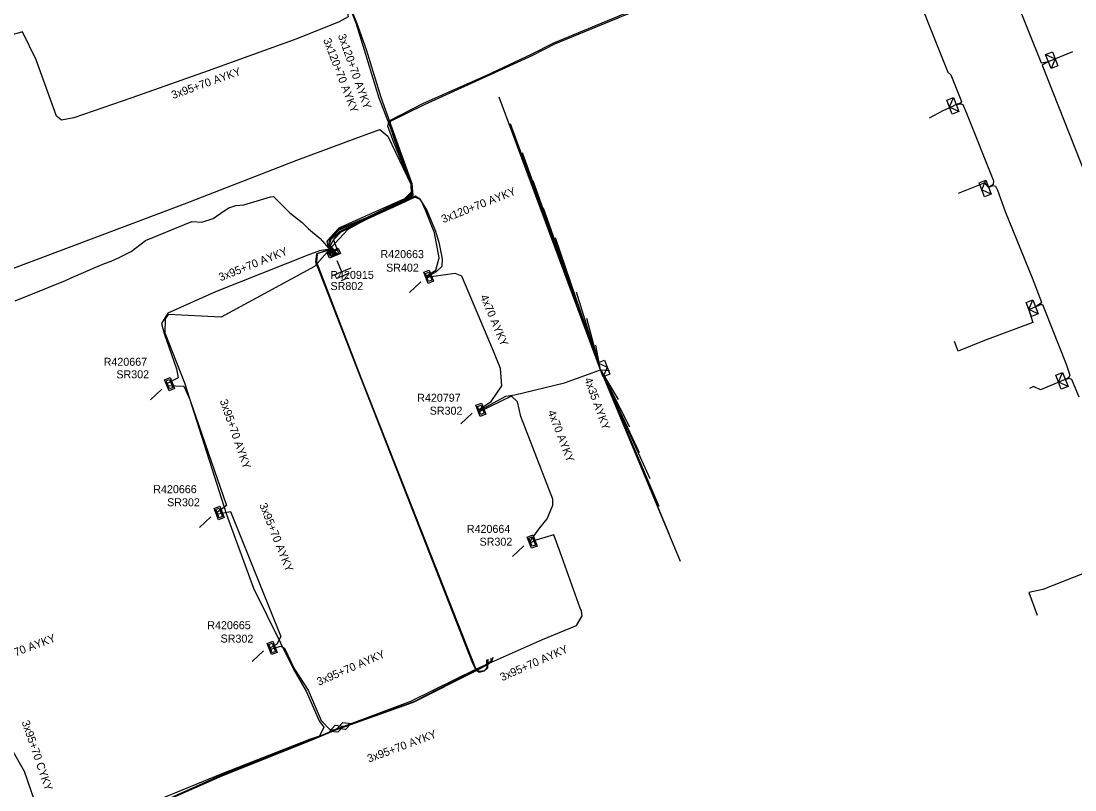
# Model space of a CAD drawing. Extents: x -540028 to -538776, y -1157064 to -1155670.
# Drawn here: x -539818.5 to -539686.8, y -1156414.7 to -1156318.7 of the extents above; entities that cross this region are included whole.
import ezdxf

# ---------------------------------------------------------------- set-up
doc = ezdxf.new("R2010")
doc.units = 0
for name, color, linetype in [('Vrstva 15', 7, 'Continuous'), ('Vrstva 19', 7, 'Continuous'), ('Vrstva 2', 7, 'Continuous'), ('Vrstva 28', 7, 'Continuous'), ('Vrstva 29', 7, 'Continuous'), ('Vrstva 30', 7, 'Continuous'), ('Vrstva 31', 7, 'Continuous'), ('Vrstva 5', 7, 'Continuous'), ('Vrstva 52', 7, 'Continuous'), ('Vrstva 59', 7, 'Continuous'), ('Vrstva 6', 7, 'Continuous'), ('Vrstva 9', 7, 'Continuous')]:
    doc.layers.add(name, color=color, linetype=linetype)

# ---------------------------------------------------------------- blocks, each defined once
blk = doc.blocks.new('17')
at = {"layer": 'Vrstva 2'}
blk.add_lwpolyline([(-1.875, 0), (0, 0.9375), (1.875, 0), (0, -0.9375)], close=True, dxfattribs=at)
blk = doc.blocks.new('132')
at = {"layer": 'Vrstva 2'}
for points in [[(-1.5, 1.5), (1.5, 1.5), (1.5, 0), (-1.5, 0)], [(-1.1, 1.2), (1.1, 1.2), (1.1, 0.3), (-1.1, 0.3)]]:
    blk.add_lwpolyline(points, close=True, dxfattribs=at)
blk = doc.blocks.new('23')
at = {"layer": 'Vrstva 2'}
blk.add_lwpolyline([(1.875, -1.8), (-1.875, -1.8), (-1.875, 0), (1.875, 0)], close=True, dxfattribs=at)
blk.add_lwpolyline([(1.875, 0), (0, -1.8), (-1.875, 0)], dxfattribs=at)
blk = doc.blocks.new('11')
at = {"layer": 'Vrstva 2'}
for p, q in [((0, -4.3), (0, -1.3)), ((-2.5, -4.3), (2.5, -4.3)), ((-1.7, -5.3), (1.7, -5.3)), ((-0.9, -6.3), (0.9, -6.3))]:
    blk.add_line(p, q, dxfattribs=at)

msp = doc.modelspace()

# ---------------------------------------------------------------- linework, layer by layer
at = {"layer": 'Vrstva 5'}
for points in [[(-539779, -1156347.91), (-539779.95, -1156346.73), (-539779.73, -1156345.88), (-539778.61, -1156344.9), (-539775.24, -1156343.33), (-539770.56, -1156341.04), (-539769.48, -1156340.33), (-539769.63, -1156339.03), (-539771.64, -1156333.68), (-539773.7, -1156328.29), (-539775.54, -1156322.32), (-539776.58, -1156318.93), (-539779.82, -1156310.93), (-539785.14, -1156296.81), (-539791.02, -1156282.92), (-539792.28, -1156279.49), (-539793.49, -1156277.84), (-539795.98, -1156277.37), (-539798.25, -1156277.83), (-539804.23, -1156280.56), (-539807.94, -1156282.09), (-539808.56, -1156282.83), (-539808.18, -1156284.31), (-539807.82, -1156285.1)], [(-539779.43, -1156348.07), (-539780.03, -1156346.76), (-539779.79, -1156345.7), (-539778.81, -1156344.68), (-539775.19, -1156343.16), (-539770.61, -1156340.97), (-539769.67, -1156340.19), (-539769.72, -1156339.08), (-539771.9, -1156333.83), (-539772.63, -1156331.81), (-539772.46, -1156331.12), (-539768.16, -1156328.91), (-539760.28, -1156325.42), (-539754.68, -1156322.8), (-539751.87, -1156321.38), (-539734.78, -1156314.29), (-539723.45, -1156309.64), (-539721.79, -1156309.32), (-539716.19, -1156306.53), (-539715.16, -1156306), (-539714.89, -1156306.22)], [(-539779.1, -1156347.94), (-539779.99, -1156346.75), (-539779.78, -1156345.83), (-539778.71, -1156344.76), (-539775.28, -1156343.26), (-539770.58, -1156340.98), (-539769.62, -1156340.26), (-539769.67, -1156339.06), (-539771.71, -1156333.71), (-539772.29, -1156331.91), (-539772.31, -1156331.17), (-539768.05, -1156329.1), (-539760.25, -1156325.54), (-539754.53, -1156322.92), (-539751.76, -1156321.51), (-539734.73, -1156314.46), (-539723.4, -1156309.72), (-539721.66, -1156309.44), (-539716.13, -1156306.73), (-539715.24, -1156306.18), (-539715.07, -1156306.3)], [(-539786.69, -1156308.23), (-539786.54, -1156308.51), (-539785.86, -1156308.98), (-539783.04, -1156307.79), (-539782.4, -1156307.75), (-539781.84, -1156308.29), (-539779.58, -1156313.15), (-539777.72, -1156317.26), (-539777.6, -1156318.14), (-539778.7, -1156318.77), (-539784.02, -1156320.88), (-539795.1, -1156324.88), (-539804.64, -1156328.28), (-539811.88, -1156330.75), (-539813.44, -1156331.06), (-539814.03, -1156330.55), (-539816.6, -1156323.5), (-539818.29, -1156320), (-539820, -1156320.5)], [(-539778.89, -1156347.86), (-539779.8, -1156346.69), (-539779.52, -1156346.16), (-539779.42, -1156345.98), (-539778.58, -1156344.99), (-539775.24, -1156343.39), (-539770.51, -1156341.13), (-539769.45, -1156340.41), (-539769.59, -1156339.02), (-539771.53, -1156333.66), (-539773.45, -1156328.23), (-539775.31, -1156322.26), (-539776.5, -1156318.89), (-539779.74, -1156310.88)], [(-539707.85, -1156311.96), (-539702.63, -1156325.04), (-539702.28, -1156325.38), (-539700.92, -1156328.7), (-539701.06, -1156328.91), (-539701.6, -1156329.1), (-539701.03, -1156329.01), (-539700.77, -1156329.1), (-539700.31, -1156330.16), (-539696.92, -1156338.64), (-539696.97, -1156339.09), (-539697.56, -1156339.42), (-539696.96, -1156339.22), (-539696.68, -1156339.3), (-539696.43, -1156339.79), (-539695.46, -1156342.46), (-539692.12, -1156350.73), (-539690.95, -1156353.8), (-539691.1, -1156353.97), (-539691.68, -1156354.36), (-539691.07, -1156354.07), (-539690.83, -1156354.08), (-539690.47, -1156354.9), (-539687.84, -1156361.53), (-539687.38, -1156362.88), (-539687.5, -1156363.17), (-539687.96, -1156363.44), (-539687.47, -1156363.29), (-539687.19, -1156363.4), (-539686.27, -1156365.6)], [(-539695.93, -1156311.52), (-539690.98, -1156323.89), (-539690.08, -1156323.73), (-539690.86, -1156324.16), (-539685.43, -1156337.88)], [(-539819.22, -1156353.62), (-539812.92, -1156351.09), (-539812.21, -1156350.76), (-539808.82, -1156349.28), (-539808.03, -1156348.96), (-539807.23, -1156348.67), (-539806.14, -1156348.15), (-539804.73, -1156347.47), (-539802.91, -1156346.09), (-539797.15, -1156343.72), (-539795.87, -1156343.77), (-539794.45, -1156343.33), (-539793.09, -1156342.39), (-539792.51, -1156341.98), (-539791.62, -1156341.72), (-539790.62, -1156341.61), (-539787.28, -1156340.64), (-539786.93, -1156340.59), (-539784.89, -1156342.64), (-539783.35, -1156343.85), (-539782.55, -1156344.61), (-539781.09, -1156345.84), (-539779.23, -1156348)], [(-539767.92, -1156350.59), (-539766.65, -1156349.77), (-539766.2, -1156348.24), (-539766.79, -1156345.12), (-539767.91, -1156342.28), (-539768.53, -1156341), (-539769.25, -1156340.66), (-539770.46, -1156341.24), (-539775.2, -1156343.43), (-539778.52, -1156345.05), (-539779.41, -1156345.99), (-539778.74, -1156347.78)], [(-539779.59, -1156348.17), (-539780.03, -1156347.26), (-539780.16, -1156347.21), (-539781.19, -1156347.37), (-539782.63, -1156347.89), (-539794.17, -1156352.5), (-539800.14, -1156355.15), (-539800.91, -1156356.43), (-539800.59, -1156357.7), (-539799.03, -1156362.12), (-539798.85, -1156363.23), (-539800.3, -1156363.99)], [(-539761.39, -1156367.25), (-539759.73, -1156366.2), (-539758.39, -1156364.23), (-539758.54, -1156362.08), (-539759.41, -1156359.9), (-539763.38, -1156350.53), (-539764.2, -1156350.21), (-539767.49, -1156350.64), (-539767.82, -1156350.82)], [(-539761.34, -1156367.38), (-539757.9, -1156365.53), (-539756.77, -1156365.34), (-539750.57, -1156363.87), (-539746.05, -1156362.22)], [(-539800.22, -1156364.21), (-539798.14, -1156364.29), (-539797.39, -1156365.94), (-539792.78, -1156379.17), (-539794.09, -1156380.14)], [(-539754.94, -1156383.75), (-539753.64, -1156381.97), (-539752.7, -1156380.86), (-539752, -1156379.14), (-539752.02, -1156378.4), (-539756.03, -1156368.06), (-539756.43, -1156366.25), (-539757.18, -1156365.52), (-539761.29, -1156367.5)], [(-539794.04, -1156380.28), (-539792.29, -1156379.93), (-539786.01, -1156395.54), (-539786.49, -1156396.48), (-539787.46, -1156397.02)], [(-539778.09, -1156406.72), (-539769.74, -1156403.61), (-539761.56, -1156399.57), (-539753.31, -1156395.93), (-539749.05, -1156394.18), (-539748.36, -1156392.96), (-539748.45, -1156392.39), (-539748.61, -1156392), (-539750.88, -1156385.59), (-539751.9, -1156382.83), (-539754.13, -1156383.51), (-539754.89, -1156383.88)], [(-539787.4, -1156397.16), (-539786.05, -1156396.76), (-539785.55, -1156396.99), (-539784.28, -1156399.63), (-539782.6, -1156402.23), (-539780.95, -1156406.05), (-539779.83, -1156407.2), (-539779.26, -1156407.15), (-539779.04, -1156407.07)], [(-539779.04, -1156407.07), (-539778.09, -1156406.72)], [(-539853.12, -1156422.78), (-539851.98, -1156422.96), (-539849.68, -1156426.99), (-539846.07, -1156436.04), (-539845, -1156436.69), (-539844.1, -1156436.81), (-539843.07, -1156436.4), (-539825.27, -1156428.44), (-539815.27, -1156424.04), (-539814.92, -1156422.74), (-539815.01, -1156421.21), (-539815.55, -1156419.63), (-539818.05, -1156412.39), (-539819.4, -1156409.99), (-539820.22, -1156409.98)]]:
    msp.add_lwpolyline(points, dxfattribs=at)
at = {"layer": 'Vrstva 52'}
for points in [[(-539690.08, -1156323.73), (-539687, -1156322.49)], [(-539701.6, -1156329.1), (-539702.04, -1156329.34), (-539703.28, -1156329.88), (-539704.99, -1156330.81)], [(-539697.56, -1156339.42), (-539698.02, -1156338.86), (-539701.34, -1156340.22)], [(-539691.68, -1156354.36), (-539692.54, -1156354.75), (-539692.04, -1156356.33), (-539698.04, -1156358.58), (-539701.35, -1156359.89), (-539701.82, -1156358.69)], [(-539687.96, -1156363.44), (-539691.07, -1156364.75), (-539691.95, -1156364.31), (-539692.42, -1156364.57)], [(-539679.72, -1156384.34), (-539680.19, -1156385.49), (-539690.76, -1156389.67), (-539692.53, -1156390.05), (-539691.46, -1156392.86)]]:
    msp.add_lwpolyline(points, dxfattribs=at)
at = {"layer": 'Vrstva 59'}
for points in [[(-539746.05, -1156362.22), (-539758.7, -1156328.16)], [(-539746.05, -1156362.22), (-539757.3, -1156331.5)], [(-539746.05, -1156362.22), (-539755.81, -1156335.13)], [(-539746.05, -1156362.22), (-539754.46, -1156338.62)], [(-539746.05, -1156362.22), (-539753.16, -1156342.06)], [(-539746.05, -1156362.22), (-539751.66, -1156345.75)], [(-539746.05, -1156362.22), (-539750.7, -1156348.85)], [(-539768.5, -1156351.23), (-539769.92, -1156352.58)], [(-539746.05, -1156362.22), (-539749.06, -1156352.53)], [(-539746.05, -1156362.22), (-539747.78, -1156355.84)], [(-539746.05, -1156362.22), (-539746.62, -1156359.16)], [(-539746.05, -1156362.22), (-539736.09, -1156386.13)], [(-539746.05, -1156362.22), (-539737.5, -1156382.66)], [(-539746.05, -1156362.22), (-539738.78, -1156379.28)], [(-539746.05, -1156362.22), (-539739.88, -1156375.8)], [(-539746.05, -1156362.22), (-539741.23, -1156372.56)], [(-539746.05, -1156362.22), (-539742.43, -1156369.37)], [(-539746.05, -1156362.22), (-539743.85, -1156365.92)], [(-539746.05, -1156362.22), (-539744.93, -1156362.31)], [(-539800.89, -1156364.65), (-539802.3, -1156366)], [(-539762.09, -1156367.64), (-539763.51, -1156368.99)], [(-539794.76, -1156380.59), (-539796.18, -1156381.94)], [(-539755.62, -1156384.2), (-539757.04, -1156385.55)], [(-539788.19, -1156397.32), (-539789.61, -1156398.68)]]:
    msp.add_lwpolyline(points, dxfattribs=at)
at = {"layer": 'Vrstva 9'}
for points in [[(-539881.36, -1156374.14), (-539881.31, -1156374.08), (-539879.87, -1156373.66), (-539864.2, -1156367.85), (-539851.61, -1156362.78), (-539842.27, -1156358.46), (-539836.17, -1156355.72), (-539823.87, -1156351.21), (-539798.04, -1156341.48), (-539784.01, -1156336.06), (-539776.7, -1156333.33), (-539773.65, -1156332.23), (-539772.62, -1156333.06), (-539769.74, -1156339.05), (-539769.7, -1156340.03), (-539770.57, -1156340.89), (-539775.43, -1156343.06), (-539778.76, -1156344.53), (-539779.9, -1156345.75), (-539780.25, -1156346.2), (-539780.15, -1156346.77), (-539779.65, -1156347.66)], [(-539767.87, -1156350.71), (-539766.56, -1156349.96), (-539765.86, -1156349.3), (-539765.79, -1156348.37), (-539766.16, -1156346.48), (-539766.62, -1156344.94), (-539767.81, -1156342.17), (-539768.58, -1156340.9), (-539769.2, -1156340.56), (-539770.58, -1156341.2), (-539775.2, -1156343.39), (-539777.65, -1156344.71), (-539779.22, -1156346.41), (-539781.81, -1156349.34), (-539793.47, -1156355.66), (-539800.07, -1156355.32), (-539800.47, -1156355.88), (-539800.51, -1156357.63), (-539798.03, -1156363.85), (-539792.81, -1156380.31), (-539789.43, -1156389.5), (-539784.38, -1156399.72), (-539782.83, -1156402.37), (-539781.2, -1156406.09), (-539780.62, -1156406.85), (-539781.19, -1156407.97), (-539782.41, -1156408.4), (-539793.39, -1156412.7), (-539806.19, -1156417.96)], [(-539779.87, -1156347.75), (-539780.08, -1156347.29), (-539781.55, -1156347.74), (-539781.68, -1156348.74), (-539776.07, -1156363.21), (-539762.14, -1156398.67), (-539761.68, -1156399.62), (-539761.22, -1156400.01), (-539760.56, -1156399.84), (-539760.15, -1156399.45), (-539760.11, -1156398.39)], [(-539779.98, -1156347.79), (-539780.16, -1156347.33), (-539781.47, -1156347.76), (-539781.57, -1156348.8), (-539776.01, -1156363.17), (-539761.64, -1156399.6), (-539761.23, -1156399.86), (-539760.57, -1156399.77), (-539760.2, -1156399.4), (-539760.27, -1156398.45)], [(-539759.51, -1156398.14), (-539759.62, -1156398.62), (-539760.06, -1156399), (-539761.6, -1156399.81), (-539769.45, -1156403.8), (-539779.17, -1156407.25), (-539782.36, -1156408.57), (-539793.3, -1156412.95), (-539805.86, -1156418.48), (-539815.48, -1156422.64), (-539825.64, -1156426.87), (-539843.97, -1156437.46), (-539854.84, -1156442.49), (-539856.09, -1156442.63), (-539856.77, -1156441.76), (-539858.17, -1156437.54)], [(-539759.76, -1156398.24), (-539759.77, -1156398.65), (-539760.65, -1156399.26), (-539761.61, -1156399.69), (-539769.4, -1156403.69), (-539779.21, -1156407.2), (-539782.34, -1156408.48), (-539793.32, -1156412.83), (-539805.9, -1156418.42), (-539815.47, -1156422.51), (-539825.7, -1156426.67), (-539844.05, -1156437.32), (-539854.91, -1156442.23), (-539855.97, -1156442.49), (-539856.71, -1156441.67), (-539858.08, -1156437.54)]]:
    msp.add_lwpolyline(points, dxfattribs=at)

# ---------------------------------------------------------------- block references
at = {"layer": 'Vrstva 15', "xscale": 0.5, "yscale": 0.5000000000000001, "rotation": 23.127180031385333}
msp.add_blockref('11', (-539779.23, -1156348), dxfattribs=at)
at = {"layer": 'Vrstva 19', "yscale": 0.5}
for p, xscale, rotation in [((-539778.09, -1156406.72), 0.5, -159.5650148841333), ((-539779.04, -1156407.07), 0.49999999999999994, 20.434985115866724)]:
    msp.add_blockref('17', p, dxfattribs=dict(at, xscale=xscale, rotation=rotation))
at = {"layer": 'Vrstva 28'}
for p, xscale, yscale, rotation in [((-539779.23, -1156348), 0.5, 0.5000000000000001, 23.127180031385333), ((-539767.88, -1156350.75), 0.5, 0.49999999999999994, -68.54048333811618), ((-539800.26, -1156364.16), 0.5, 0.5, -68.41753609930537), ((-539761.37, -1156367.36), 0.5000000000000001, 0.5, -68.54344439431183), ((-539794.07, -1156380.25), 0.5, 0.5, -68.5260722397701), ((-539754.94, -1156383.82), 0.5, 0.5, -68.5436972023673), ((-539787.45, -1156397.11), 0.5, 0.5, -68.60207495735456)]:
    msp.add_blockref('132', p, dxfattribs=dict(at, xscale=xscale, yscale=yscale, rotation=rotation))
at = {"layer": 'Vrstva 31'}
for p, xscale, yscale, rotation in [((-539690.08, -1156323.73), 0.5, 0.5, 111.03751109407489), ((-539701.6, -1156329.1), 0.49999999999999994, 0.5000000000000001, -68.96248889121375), ((-539697.56, -1156339.42), 0.49999999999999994, 0.5000000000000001, -68.96248890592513), ((-539691.68, -1156354.36), 0.5, 0.5, -68.96248895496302), ((-539746.05, -1156362.22), 0.5, 0.5, 111.48544446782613), ((-539687.96, -1156363.44), 0.49999999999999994, 0.5000000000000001, -68.96248884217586)]:
    msp.add_blockref('23', p, dxfattribs=dict(at, xscale=xscale, yscale=yscale, rotation=rotation))

# ---------------------------------------------------------------- texts
at = {"layer": 'Vrstva 29'}
for s, p in [('R420663', (-539773.55, -1156348.28)), ('R420667', (-539808.15, -1156361.73)), ('R420797', (-539768.96, -1156366.22)), ('R420666', (-539801.95, -1156377.64)), ('R420664', (-539762.76, -1156382.6)), ('R420665', (-539795.2, -1156394.63))]:
    msp.add_text(s, height=1, dxfattribs=at).set_placement(p)
msp.add_text('R420915', height=1, rotation=0.245, dxfattribs=at).set_placement((-539779.82, -1156350.89))
at = {"layer": 'Vrstva 30'}
for s, rotation, p in [('SR402', 359.983, (-539772.85, -1156349.97)), ('SR802', 0.05, (-539779.8, -1156352.27)), ('SR302', 0.206, (-539806.56, -1156363.3)), ('SR302', 359.848, (-539767.4, -1156367.83)), ('SR302', 359.834, (-539800.22, -1156379.27)), ('SR302', 0.016, (-539761.17, -1156384.2)), ('SR302', 359.645, (-539793.54, -1156396.29))]:
    msp.add_text(s, height=1, rotation=rotation, dxfattribs=at).set_placement(p)
at = {"layer": 'Vrstva 6'}
for s, rotation, p in [('3x120+70 AYKY', 289.483, (-539778.89, -1156320.47)), ('3x120+70 AYKY', 290.953, (-539780.73, -1156321.02)), ('3x95+70 AYKY', 19.648, (-539799.48, -1156328.42)), ('3x120+70 AYKY', 21.491, (-539765.71, -1156343.92)), ('3x95+70 AYKY', 21.768, (-539793.53, -1156351.18)), ('4x70 AYKY', 292.948, (-539761.12, -1156353.08)), ('4x35 AYKY', 290.057, (-539748.1, -1156363.4)), ('3x95+70 AYKY', 289.211, (-539793.66, -1156366.1)), ('4x70 AYKY', 291.163, (-539752.68, -1156367.48)), ('3x95+70 AYKY', 291.903, (-539788.73, -1156379.1)), ('3x95+70 AYKY', 20.634, (-539822.59, -1156399.33)), ('3x95+70 AYKY', 23.803, (-539758.35, -1156401.14)), ('3x95+70 AYKY', 23.369, (-539781.25, -1156401.7)), ('3x95+70 CYKY', 289.01, (-539818.42, -1156406.21)), ('3x95+70 AYKY', 20.435, (-539774.99, -1156411.3))]:
    msp.add_text(s, height=1, rotation=rotation, dxfattribs=at).set_placement(p)

doc.saveas('drawing.dxf')
